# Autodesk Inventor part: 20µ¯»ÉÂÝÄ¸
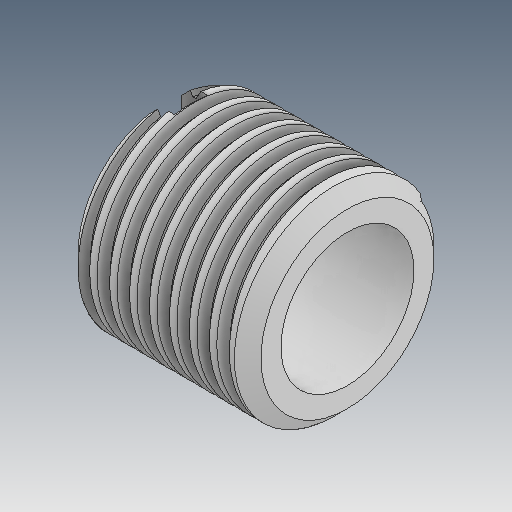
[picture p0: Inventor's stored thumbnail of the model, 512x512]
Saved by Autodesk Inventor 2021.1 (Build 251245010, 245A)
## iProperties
Created: 2019-12
Part Number: 20µ¯»ÉÂÝÄ¸
Material: Ogólny
Document SubType Name: Modeling
Designer: user
Density: 1 g/cm^3
Appearance: Domyślna
Author: user
Revision Number: ÈÎºÎ
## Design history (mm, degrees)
feature "ÊäÈë1"
node "Bryła1"
